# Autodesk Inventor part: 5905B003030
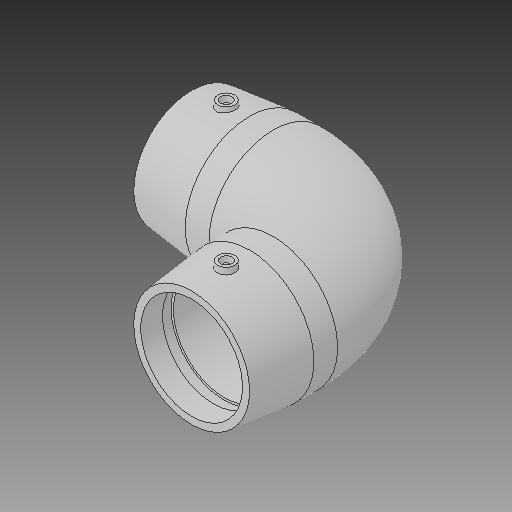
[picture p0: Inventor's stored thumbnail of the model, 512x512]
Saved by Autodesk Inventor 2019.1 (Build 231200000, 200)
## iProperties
Created: 2017-06
Part Number: 5905B003030
Material: Generic
Description: PLASSON 90° ELBOW ASTM 3''
Document SubType Name: Modeling
Designer: KIM
Mass: 55.0731 g
Surface Area: 148.067 cm^2
Volume: 55.0731 cm^3
Density: 1 g/cm^3
Appearance: Default
Author: KIM
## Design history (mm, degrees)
derived "5905B.ipt"
feature "Solid1::5905B.ipt"
tag "TaggingFeature1"
body "Solid1"
other parameters: "d_" = 88.7, "L_" = 201.93, "L_1" = 71.12, "D_" = 112.268, "A_" = 58.42, "d2" = 112.268, "d4" = 50.4825, "d5" = 101.0412, "d8" = 168 deg, "d10" = 28.448, "d11" = 9.48267, "d14" = 17.6296, "d18" = 88.7, "d19" = 3.52592, "d20" = 168 deg, "d22" = 103.28656, "d23" = 112.268, "d24" = 100.18796, "d29" = 58.42, "d30" = 15, "d31" = 121.158, "d34" = 5 deg, "d35" = 15, "d39" = 5 deg, "d41" = 4, "d42" = 14, "d43" = 0, "d45" = 4, "d46" = 14, "d47" = 0, "d49" = 88.7, "d50" = 75.395, "d51" = 28.448, "d52" = 71.12, "d54" = 90 deg, "d65" = 88.7, "d67" = 45 deg, "d71" = 90 deg, "d75" = 5.6134, "d82" = 45 deg, "d83" = 71.12, "d84" = 101.0412, "d86" = 50.5206, "d87" = 90 deg, "d90" = 71.12, "d91" = 0, "d92" = 71.12, "d93" = 0, "d94" = 90 deg, "d95" = 51.64328, "d98" = 201.93, "d101" = 3, "d102" = 0, "d103" = 3, "d104" = 0, "d105" = 20.6248, "d106" = 5.1562, "d107" = 201.93, "d110" = 39.116
